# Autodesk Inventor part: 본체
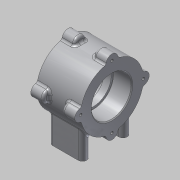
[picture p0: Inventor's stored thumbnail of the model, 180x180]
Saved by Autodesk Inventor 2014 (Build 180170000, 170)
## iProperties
Created: 2015-03
Part Number: 본체
Material: 알루미늄 6061
Document SubType Name: Modeling
Designer: MYHOME
Density: 2.71 g/cm^3
Appearance: 알루미늄 - 평지
Mass: 454.972 g
Surface Area: 336.673 cm^2
Volume: 167.886 cm^3
Author: MYHOME
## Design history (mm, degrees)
sketch "스케치2"
  geometry: C1 r 37 at (0, 0); 1 further point
  constraints: 1 centre point, 1 coincident
  dimensions: "d0" = 74 diameter of C1
extrude "돌출1" new body sketch "스케치2" stored distance "d1" = 52; taper "d2" = 0 deg
node "작업 평면2"
sketch "스케치5"
  geometry: L1 (15, -24)-(-15, -24); L2 (15, -29)-(-15, -29); L3 (-15, -19)-(15, -19); L4 (15, 24)-(-15, 24); L5 (15, 29)-(-15, 29); L6 (-15, 19)-(15, 19); A1 r 5 centre (15, -24) between (15, -29) and (15, -19); A2 r 5 centre (-15, -24) between (-15, -19) and (-15, -29); A3 r 5 centre (15, 24) between (15, 19) and (15, 29); A4 r 5 centre (-15, 24) between (-15, 29) and (-15, 19); 3 further points
  constraints: 16 end point, 8 point on circle, 8 tangent, 4 centre point, 4 parallel, 2 midpoint, 2 vertical alignment, 1 equal radius, 1 horizontal
  dimensions: "d17" = 5 radius of A4; "d18" = 48 distance of L4.start L1.start; "d19" = 40 dimension on A3 A4; "d20" = 24 distance of point (0, 0) point (0, -24)
extrude "돌출3" join sketch "스케치5" stored distance "d21" = 15; taper "d22" = 0 deg
sketch "스케치6"
  geometry: C1 r 23.5 at (0, 0); A1 r 37 centre (0, 0) between (0, 37) and (0, 37) reference
  constraints: 1 centre point, 1 coincident
  dimensions: "d23" = 47 diameter of C1
extrude "돌출4" cut sketch "스케치6" distance "d24" = 22; taper "d25" = 0 deg
hole "구멍2" diameter "d29" = 42; stored, may be unused: countersink angle "d33" = 90 deg, drill point angle "d35" = 0 deg; dims "d27" = 10, "d28" = 10, "d30" = 8, "d31" = 47, "d32" = 22, "d34" = 30
fillet "모깎기1" dims "d36" = 0.3
sketch "스케치8"
  geometry: L1 (0, 0)-(-37.594, 0); L2 (0, 0)-(-26.163, 26.163); A1 r 37 centre (0, 0) between (37, 0) and (37, 0) reference; 4 further points
  constraints: 4 end point, 1 coincident, 1 horizontal, 1 point on circle
  dimensions: "d37" = 45 deg angle of L1 L2
sketch "스케치10"
  geometry: A1 r 5 centre (15, -24) between (15, -29) and (15, -19) reference; A2 r 5 centre (-15, -24) between (-15, -19) and (-15, -29) reference; A3 r 5 centre (-15, 24) between (-15, 29) and (-15, 19) reference; A4 r 5 centre (15, 24) between (15, 19) and (15, 29) reference; 5 further points
  constraints: 4 coincident
hole "구멍3" sketch "스케치10" at (-15, 24), (15, 24), (15, -24), (-15, -24) diameter "d40" = 4.134; stored, may be unused: countersink angle "d44" = 90 deg, drill point angle "d46" = 118 deg; dims "d41" = 6, "d42" = 47, "d43" = 22, "d45" = 8
chamfer "모따기1" distance "d47" = 1; stored, may be unused: second distance "d48" = 2, angle "d49" = 45 deg
fillet "모깎기4" dims "d52" = 3
sketch "스케치11"
  geometry: C1 r 7 at (-37, 0); C2 r 7 at (0, -37); C3 r 7 at (37, 0); C4 r 7 at (0, 37); A1 r 37 centre (0, 0) between (-37, 0) and (0, -37) reference
  constraints: 4 centre point, 4 point on circle, 2 horizontal alignment, 2 vertical alignment
  dimensions: "d55" = 7 radius of C1; "d56" = 7 radius of C2; "d57" = 7 radius of C3; "d58" = 7 radius of C4
extrude "돌출5" join sketch "스케치11" distance "d59" = 15; taper "d60" = 0 deg
sketch "스케치12"
  geometry: A1 r 7 centre (-37, 0) between (-36.338, 6.969) and (-36.338, -6.969) reference; A2 r 7 centre (0, -37) between (-6.969, -36.338) and (6.969, -36.338) reference; A3 r 7 centre (37, 0) between (36.338, -6.969) and (36.338, 6.969) reference; A4 r 7 centre (0, 37) between (6.969, 36.338) and (-6.969, 36.338) reference; 4 further points
  constraints: 4 coincident
hole "구멍4" sketch "스케치12" at (0, 37), (-37, 0), (0, -37), (37, 0) diameter "d61" = 3.242; stored, may be unused: countersink angle "d65" = 90 deg, drill point angle "d67" = 118 deg; dims "d62" = 8, "d63" = 4, "d64" = 2, "d66" = 11
fillet "모깎기5" dims "d68" = 3
fillet "모깎기6" dims "d69" = 3
node "솔리드1"
mirror "대칭2"
other parameters: "d16" = -56
